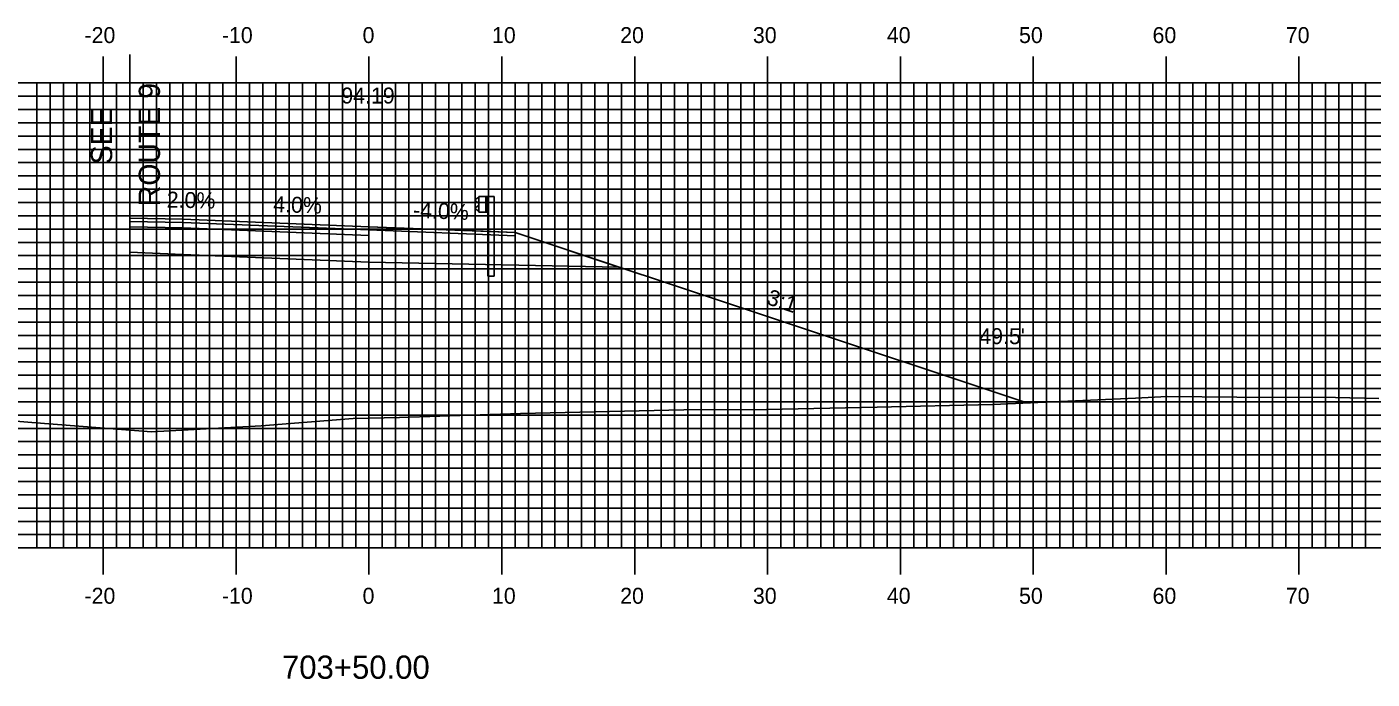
# Model space of a CAD drawing. Extents: x 853329 to 853673, y 364366 to 364586.
# Drawn here: x 853469.5 to 853570.7, y 364428.9 to 364478 of the extents above; entities that cross this region are included whole.
import ezdxf

# ---------------------------------------------------------------- set-up
doc = ezdxf.new("R2010")
doc.units = 0
for name, color, linetype in [('ANNOTATION', 7, 'Continuous'), ('D_Guardrail_Beam_Rt', 7, 'Continuous'), ('D_Roadway_Centerline_Text', 7, 'Continuous'), ('D_Roadway_Edge_Shoulder', 7, 'Continuous'), ('D_Roadway_Pavement', 7, 'Continuous'), ('D_Roadway_SlopeLines', 7, 'Continuous'), ('D_Roadway_SubGrade', 7, 'Continuous'), ('D_Text_Standard', 7, 'Continuous'), ('H_V ANNOTATION', 7, 'Continuous'), ('MAJOR', 7, 'Continuous'), ('MINOR', 7, 'Continuous'), ('S_Roadway_Centerline', 7, 'Continuous')]:
    doc.layers.add(name, color=color, linetype=linetype)

msp = doc.modelspace()

# ---------------------------------------------------------------- linework, layer by layer
at = {"layer": 'D_Guardrail_Beam_Rt'}
for p, q in [((853503.39, 364465.13), (853503.24, 364465.03)), ((853503.24, 364464.89), (853503.44, 364464.75)), ((853503.48, 364465.15), (853503.4, 364465.14)), ((853503.47, 364464.69), (853503.47, 364464.62)), ((853503.48, 364465.24), (853504.16, 364465.24)), ((853503.48, 364464.07), (853503.48, 364465.24)), ((853504, 364465.24), (853504, 364464.07)), ((853504.1, 364465.24), (853504.1, 364464.07)), ((853504.16, 364465.24), (853504.63, 364465.24)), ((853504.16, 364465.24), (853504.16, 364464.07)), ((853504.63, 364465.24), (853504.63, 364459.24)), ((853503.44, 364464.56), (853503.24, 364464.42)), ((853503.24, 364464.28), (853503.39, 364464.18)), ((853503.4, 364464.17), (853503.48, 364464.15)), ((853504.16, 364464.07), (853503.48, 364464.07)), ((853504.14, 364459.24), (853504.14, 364464.07)), ((853504.14, 364459.24), (853504.63, 364459.24))]:
    msp.add_line(p, q, dxfattribs=at)
for centre, major_axis, start_param, end_param in [((853503.29, 364464.96), (-0.0877, 0), 5.323254, 7.243116), ((853503.41, 364465.1), (-0.0417, 0), 4.907132, 5.323254), ((853503.39, 364464.69), (0.0789, 0), 0, 0.959931), ((853503.39, 364464.62), (0.0789, 0), 5.323254, 6.283185), ((853503.29, 364464.35), (-0.0877, 0), 5.323254, 7.243116), ((853503.41, 364464.21), (-0.0417, 0), 0.959931, 1.376053)]:
    msp.add_ellipse(centre, major_axis=major_axis, ratio=0.995501, start_param=start_param, end_param=end_param, dxfattribs=at)
at = {"layer": 'D_Roadway_Edge_Shoulder'}
for points in [[(853481.2, 364463.53), (853477.2, 364463.61), (853477.2, 364463.36), (853481.2, 364463.28)], [(853495.2, 364462.97), (853503.2, 364462.65), (853503.2, 364462.65), (853506.2, 364462.53), (853506.2, 364462.28), (853495.2, 364462.72)], [(853495.2, 364462.97), (853506.2, 364462.53), (853506.2, 364462.28), (853495.2, 364462.72)], [(853495.2, 364462.97), (853503.2, 364462.65), (853503.2, 364462.65), (853506.2, 364462.53), (853506.2, 364462.28), (853495.2, 364462.72)]]:
    msp.add_lwpolyline(points, close=True, dxfattribs=at)
at = {"layer": 'D_Roadway_Pavement'}
msp.add_lwpolyline([(853495.2, 364462.72), (853495.2, 364462.31)], dxfattribs=at)
msp.add_lwpolyline([(853495.2, 364462.72), (853495.2, 364462.31)], dxfattribs=at)
msp.add_lwpolyline([(853495.2, 364462.72), (853495.2, 364462.31)], dxfattribs=at)
msp.add_lwpolyline([(853495.2, 364462.72), (853495.2, 364462.31)], dxfattribs=at)
msp.add_lwpolyline([(853495.2, 364462.72), (853495.2, 364462.31)], dxfattribs=at)
msp.add_lwpolyline([(853495.2, 364462.72), (853495.2, 364462.31)], dxfattribs=at)
msp.add_lwpolyline([(853495.2, 364462.72), (853495.2, 364462.31)], dxfattribs=at)
msp.add_lwpolyline([(853495.2, 364462.72), (853495.2, 364462.31)], dxfattribs=at)
msp.add_lwpolyline([(853495.2, 364462.72), (853495.2, 364462.31)], dxfattribs=at)
msp.add_lwpolyline([(853495.2, 364462.72), (853495.2, 364462.31)], dxfattribs=at)
msp.add_lwpolyline([(853495.2, 364462.72), (853495.2, 364462.31)], dxfattribs=at)
msp.add_lwpolyline([(853495.2, 364462.72), (853495.2, 364462.31)], dxfattribs=at)
msp.add_lwpolyline([(853495.2, 364462.72), (853495.2, 364462.31)], dxfattribs=at)
msp.add_lwpolyline([(853495.2, 364462.72), (853495.2, 364462.31)], dxfattribs=at)
at = {"layer": 'D_Roadway_SlopeLines'}
for p, q in [((853495.2, 364462.97), (853481.2, 364463.53)), ((853495.2, 364462.72), (853481.2, 364463.28)), ((853481.2, 364462.87), (853495.2, 364462.31))]:
    msp.add_line(p, q, dxfattribs=at)
for points in [[(853481.2, 364463.53), (853481.2, 364460.87), (853495.2, 364460.31)], [(853506.2, 364462.53), (853544.71, 364449.7)], [(853506.2, 364462.53), (853544.71, 364449.7)]]:
    msp.add_lwpolyline(points, dxfattribs=at)
at = {"layer": 'D_Roadway_SubGrade'}
msp.add_line((853477.2, 364475.93), (853477.2, 364460.97), dxfattribs=at)
for points in [[(853481.2, 364462.87), (853477.2, 364462.95), (853477.2, 364463.36), (853477.2, 364461.05), (853481.2, 364460.87)], [(853495.2, 364462.31), (853495.2, 364462.72), (853506.2, 364462.28), (853506.2, 364462.53), (853514.01, 364459.93), (853495.2, 364460.31)]]:
    msp.add_lwpolyline(points, close=True, dxfattribs=at)
at = {"layer": 'MAJOR'}
for p, q in [((853475.2, 364475.79), (853475.2, 364473.79)), ((853485.2, 364475.79), (853485.2, 364473.79)), ((853495.2, 364475.79), (853495.2, 364473.79)), ((853505.2, 364475.79), (853505.2, 364473.79)), ((853515.2, 364475.79), (853515.2, 364473.79)), ((853525.2, 364475.79), (853525.2, 364473.79)), ((853535.2, 364475.79), (853535.2, 364473.79)), ((853545.2, 364475.79), (853545.2, 364473.79)), ((853555.2, 364475.79), (853555.2, 364473.79)), ((853565.2, 364475.79), (853565.2, 364473.79)), ((853355.2, 364473.79), (853635.2, 364473.79)), ((853355.2, 364473.79), (853635.2, 364473.79)), ((853475.2, 364438.79), (853475.2, 364473.79)), ((853485.2, 364438.79), (853485.2, 364473.79)), ((853495.2, 364438.79), (853495.2, 364473.79)), ((853505.2, 364438.79), (853505.2, 364473.79)), ((853515.2, 364438.79), (853515.2, 364473.79)), ((853525.2, 364438.79), (853525.2, 364473.79)), ((853535.2, 364438.79), (853535.2, 364473.79)), ((853545.2, 364438.79), (853545.2, 364473.79)), ((853555.2, 364438.79), (853555.2, 364473.79)), ((853565.2, 364438.79), (853565.2, 364473.79)), ((853355.2, 364468.79), (853635.2, 364468.79)), ((853355.2, 364463.79), (853635.2, 364463.79)), ((853355.2, 364458.79), (853635.2, 364458.79)), ((853355.2, 364453.79), (853635.2, 364453.79)), ((853355.2, 364448.79), (853635.2, 364448.79)), ((853355.2, 364443.79), (853635.2, 364443.79)), ((853355.2, 364438.79), (853635.2, 364438.79)), ((853355.2, 364438.79), (853635.2, 364438.79)), ((853475.2, 364436.78), (853475.2, 364438.79)), ((853485.2, 364436.78), (853485.2, 364438.79)), ((853495.2, 364436.78), (853495.2, 364438.79)), ((853505.2, 364436.78), (853505.2, 364438.79)), ((853515.2, 364436.78), (853515.2, 364438.79)), ((853525.2, 364436.78), (853525.2, 364438.79)), ((853535.2, 364436.78), (853535.2, 364438.79)), ((853545.2, 364436.78), (853545.2, 364438.79)), ((853555.2, 364436.78), (853555.2, 364438.79)), ((853565.2, 364436.78), (853565.2, 364438.79))]:
    msp.add_line(p, q, dxfattribs=at)
at = {"layer": 'MINOR'}
for p, q in [((853470.2, 364438.79), (853470.2, 364473.79)), ((853471.2, 364438.79), (853471.2, 364473.79)), ((853472.2, 364438.79), (853472.2, 364473.79)), ((853473.2, 364438.79), (853473.2, 364473.79)), ((853474.2, 364438.79), (853474.2, 364473.79)), ((853476.2, 364438.79), (853476.2, 364473.79)), ((853477.2, 364438.79), (853477.2, 364473.79)), ((853478.2, 364438.79), (853478.2, 364473.79)), ((853479.2, 364438.79), (853479.2, 364473.79)), ((853480.2, 364438.79), (853480.2, 364473.79)), ((853481.2, 364438.79), (853481.2, 364473.79)), ((853482.2, 364438.79), (853482.2, 364473.79)), ((853483.2, 364438.79), (853483.2, 364473.79)), ((853484.2, 364438.79), (853484.2, 364473.79)), ((853486.2, 364438.79), (853486.2, 364473.79)), ((853487.2, 364438.79), (853487.2, 364473.79)), ((853488.2, 364438.79), (853488.2, 364473.79)), ((853489.2, 364438.79), (853489.2, 364473.79)), ((853490.2, 364438.79), (853490.2, 364473.79)), ((853491.2, 364438.79), (853491.2, 364473.79)), ((853492.2, 364438.79), (853492.2, 364473.79)), ((853493.2, 364438.79), (853493.2, 364473.79)), ((853494.2, 364438.79), (853494.2, 364473.79)), ((853496.2, 364438.79), (853496.2, 364473.79)), ((853497.2, 364438.79), (853497.2, 364473.79)), ((853498.2, 364438.79), (853498.2, 364473.79)), ((853499.2, 364438.79), (853499.2, 364473.79)), ((853500.2, 364438.79), (853500.2, 364473.79)), ((853501.2, 364438.79), (853501.2, 364473.79)), ((853502.2, 364438.79), (853502.2, 364473.79)), ((853503.2, 364438.79), (853503.2, 364473.79)), ((853504.2, 364438.79), (853504.2, 364473.79)), ((853506.2, 364438.79), (853506.2, 364473.79)), ((853507.2, 364438.79), (853507.2, 364473.79)), ((853508.2, 364438.79), (853508.2, 364473.79)), ((853509.2, 364438.79), (853509.2, 364473.79)), ((853510.2, 364438.79), (853510.2, 364473.79)), ((853511.2, 364438.79), (853511.2, 364473.79)), ((853512.2, 364438.79), (853512.2, 364473.79)), ((853513.2, 364438.79), (853513.2, 364473.79)), ((853514.2, 364438.79), (853514.2, 364473.79)), ((853516.2, 364438.79), (853516.2, 364473.79)), ((853517.2, 364438.79), (853517.2, 364473.79)), ((853518.2, 364438.79), (853518.2, 364473.79)), ((853519.2, 364438.79), (853519.2, 364473.79)), ((853520.2, 364438.79), (853520.2, 364473.79)), ((853521.2, 364438.79), (853521.2, 364473.79)), ((853522.2, 364438.79), (853522.2, 364473.79)), ((853523.2, 364438.79), (853523.2, 364473.79)), ((853524.2, 364438.79), (853524.2, 364473.79)), ((853526.2, 364438.79), (853526.2, 364473.79)), ((853527.2, 364438.79), (853527.2, 364473.79)), ((853528.2, 364438.79), (853528.2, 364473.79)), ((853529.2, 364438.79), (853529.2, 364473.79)), ((853530.2, 364438.79), (853530.2, 364473.79)), ((853531.2, 364438.79), (853531.2, 364473.79)), ((853532.2, 364438.79), (853532.2, 364473.79)), ((853533.2, 364438.79), (853533.2, 364473.79)), ((853534.2, 364438.79), (853534.2, 364473.79)), ((853536.2, 364438.79), (853536.2, 364473.79)), ((853537.2, 364438.79), (853537.2, 364473.79)), ((853538.2, 364438.79), (853538.2, 364473.79)), ((853539.2, 364438.79), (853539.2, 364473.79)), ((853540.2, 364438.79), (853540.2, 364473.79)), ((853541.2, 364438.79), (853541.2, 364473.79)), ((853542.2, 364438.79), (853542.2, 364473.79)), ((853543.2, 364438.79), (853543.2, 364473.79)), ((853544.2, 364438.79), (853544.2, 364473.79)), ((853546.2, 364438.79), (853546.2, 364473.79)), ((853547.2, 364438.79), (853547.2, 364473.79)), ((853548.2, 364438.79), (853548.2, 364473.79)), ((853549.2, 364438.79), (853549.2, 364473.79)), ((853550.2, 364438.79), (853550.2, 364473.79)), ((853551.2, 364438.79), (853551.2, 364473.79)), ((853552.2, 364438.79), (853552.2, 364473.79)), ((853553.2, 364438.79), (853553.2, 364473.79)), ((853554.2, 364438.79), (853554.2, 364473.79)), ((853556.2, 364438.79), (853556.2, 364473.79)), ((853557.2, 364438.79), (853557.2, 364473.79)), ((853558.2, 364438.79), (853558.2, 364473.79)), ((853559.2, 364438.79), (853559.2, 364473.79)), ((853560.2, 364438.79), (853560.2, 364473.79)), ((853561.2, 364438.79), (853561.2, 364473.79)), ((853562.2, 364438.79), (853562.2, 364473.79)), ((853563.2, 364438.79), (853563.2, 364473.79)), ((853564.2, 364438.79), (853564.2, 364473.79)), ((853566.2, 364438.79), (853566.2, 364473.79)), ((853567.2, 364438.79), (853567.2, 364473.79)), ((853568.2, 364438.79), (853568.2, 364473.79)), ((853569.2, 364438.79), (853569.2, 364473.79)), ((853570.2, 364438.79), (853570.2, 364473.79)), ((853355.2, 364472.79), (853635.2, 364472.79)), ((853355.2, 364471.79), (853635.2, 364471.79)), ((853355.2, 364470.79), (853635.2, 364470.79)), ((853355.2, 364469.79), (853635.2, 364469.79)), ((853355.2, 364467.79), (853635.2, 364467.79)), ((853355.2, 364466.79), (853635.2, 364466.79)), ((853355.2, 364465.79), (853635.2, 364465.79)), ((853355.2, 364464.79), (853635.2, 364464.79)), ((853355.2, 364462.79), (853635.2, 364462.79)), ((853355.2, 364461.79), (853635.2, 364461.79)), ((853355.2, 364460.79), (853635.2, 364460.79)), ((853355.2, 364459.79), (853635.2, 364459.79)), ((853355.2, 364457.79), (853635.2, 364457.79)), ((853355.2, 364456.79), (853635.2, 364456.79)), ((853355.2, 364455.79), (853635.2, 364455.79)), ((853355.2, 364454.79), (853635.2, 364454.79)), ((853355.2, 364452.79), (853635.2, 364452.79)), ((853355.2, 364451.79), (853635.2, 364451.79)), ((853355.2, 364450.79), (853635.2, 364450.79)), ((853355.2, 364449.79), (853635.2, 364449.79)), ((853355.2, 364447.79), (853635.2, 364447.79)), ((853355.2, 364446.79), (853635.2, 364446.79)), ((853355.2, 364445.79), (853635.2, 364445.79)), ((853355.2, 364444.79), (853635.2, 364444.79)), ((853355.2, 364442.79), (853635.2, 364442.79)), ((853355.2, 364441.79), (853635.2, 364441.79)), ((853355.2, 364440.79), (853635.2, 364440.79)), ((853355.2, 364439.79), (853635.2, 364439.79))]:
    msp.add_line(p, q, dxfattribs=at)
at = {"layer": 'S_Roadway_Centerline'}
msp.add_lwpolyline([(853452.13, 364449.72), (853469.83, 364448.24), (853478.82, 364447.54), (853487.09, 364447.97), (853494.02, 364448.53), (853497.51, 364448.61), (853506.61, 364448.92), (853518.91, 364449.18), (853525.11, 364449.22), (853533.46, 364449.39), (853542.16, 364449.59), (853552.89, 364450.05), (853555.27, 364450.19), (853560.53, 364450.13), (853567.94, 364450.11), (853571.2, 364450.03)], dxfattribs=at)

# ---------------------------------------------------------------- texts
at = {"layer": 'ANNOTATION'}
for s, height, rotation, p in [('ROUTE 9', 1.6, 90, (853479.47, 364464.51)), ('SEE', 1.6, 90, (853475.87, 364467.66)), ('2.0%', 1.2, 358.8542, (853479.97, 364464.41)), ('4.0%', 1.2, 358.0214, (853487.98, 364464.08)), ('-4.0%', 1.2, 357.7094, (853498.5, 364463.64)), ('3:1', 1.2, 341.5651, (853525.06, 364457.16))]:
    msp.add_text(s, height=height, rotation=rotation, dxfattribs=at).set_placement(p)
at = {"layer": 'D_Roadway_Centerline_Text'}
msp.add_text('94.19', height=1.2, dxfattribs=at).set_placement((853493.12, 364472.24))
at = {"layer": 'D_Text_Standard'}
msp.add_text("49.5'", height=1.2, dxfattribs=at).set_placement((853541.14, 364454.13))
at = {"layer": 'H_V ANNOTATION'}
for s, height, p in [('-20', 1.2, (853473.79, 364476.79)), ('-10', 1.2, (853484.13, 364476.79)), ('0', 1.2, (853494.72, 364476.79)), ('10', 1.2, (853504.46, 364476.79)), ('20', 1.2, (853514.11, 364476.79)), ('30', 1.2, (853524.1, 364476.79)), ('40', 1.2, (853534.18, 364476.79)), ('50', 1.2, (853544.13, 364476.79)), ('60', 1.2, (853554.18, 364476.79)), ('70', 1.2, (853564.21, 364476.79)), ('-20', 1.2, (853473.79, 364434.59)), ('-10', 1.2, (853484.13, 364434.59)), ('0', 1.2, (853494.72, 364434.59)), ('10', 1.2, (853504.46, 364434.59)), ('20', 1.2, (853514.11, 364434.59)), ('30', 1.2, (853524.1, 364434.59)), ('40', 1.2, (853534.18, 364434.59)), ('50', 1.2, (853544.13, 364434.59)), ('60', 1.2, (853554.18, 364434.59)), ('70', 1.2, (853564.21, 364434.59)), ('703+50.00', 1.75, (853488.65, 364428.94))]:
    msp.add_text(s, height=height, dxfattribs=at).set_placement(p)

doc.saveas('drawing.dxf')
